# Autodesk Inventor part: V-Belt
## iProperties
Created: 2011-05
Part Number: V-Belt
Material: Rubber
Document SubType Name: Modeling
Designer: 904Chiaki
Density: 0.93 g/cm^3
CustomPartVersion: 1
Author: 904Chiaki
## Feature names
1. Belt
